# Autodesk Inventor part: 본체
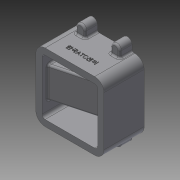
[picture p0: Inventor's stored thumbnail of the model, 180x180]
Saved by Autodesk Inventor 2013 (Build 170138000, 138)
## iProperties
Created: 2018-01
Part Number: 본체
Material: 일반
Document SubType Name: Modeling
Designer: Administrator
Density: 1 g/cm^3
Author: Administrator
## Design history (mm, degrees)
sketch "스케치1"
  geometry: L1 (55, 55)-(-55, 55); L2 (-55, 55)-(-55, -55); L3 (-55, -55)-(55, -55); L4 (55, -55)-(55, 55); L5 (55, 55)-(-55, -55); L6 (-55, 55)-(55, -55); 1 further point
  constraints: 12 end point, 2 midpoint, 2 parallel, 1 horizontal, 1 perpendicular
  dimensions: "d0" = 110 distance of L3.end L2.end; "d1" = 110 distance of L2.end L1.end
extrude "돌출1" new body sketch "스케치1" distance "d2" = 65; taper "d3" = 0 deg
sketch "스케치2"
  geometry: L1 (-55, -55)-(55, -55) reference; L2 (55, -55)-(55, 55) reference; L3 (55, 55)-(-55, 55) reference; L4 (-55, 55)-(-55, -55) reference; L5 (-45, 45)-(45, 45); L6 (45, 45)-(45, -45); L7 (45, -45)-(-45, -45); L8 (-45, -45)-(-45, 45); 1 further point
  constraints: 8 end point, 3 other
  dimensions: "d4" = 10 distance between parallel lines of L2 L6
extrude "돌출2" cut sketch "스케치2" distance "d5" = 65; taper "d6" = 0 deg
sketch "스케치3"
  geometry: L1 (55, 55)-(-55, 55) reference; L2 (-55, -55)-(55, -55) reference; L3 (-35.5, 55)-(-35.5, 65); L4 (-20.5, 65)-(-20.5, 55); L5 (-55, 55)-(-55, -55) reference; L6 (55, -55)-(55, 55) reference; L7 (-55, 0)-(55, 0); L8 (0, 55)-(0, -55); L9 (35.5, 55)-(35.5, 65); L10 (20.5, 65)-(20.5, 55); L11 (20.5, -65)-(20.5, -55); L12 (35.5, -55)-(35.5, -65); L13 (-35.5, -55)-(-35.5, -65); L14 (-20.5, -65)-(-20.5, -55); L15 (-35.5, 55)-(-20.5, 55); L16 (20.5, 55)-(35.5, 55); L17 (-35.5, -55)-(-20.5, -55); L18 (20.5, -55)-(35.5, -55); A1 r 7.5 centre (-28, 65) between (-20.5, 65) and (-35.5, 65); A2 r 7.5 centre (28, 65) between (35.5, 65) and (20.5, 65); A3 r 7.5 centre (28, -65) between (20.5, -65) and (35.5, -65); A4 r 7.5 centre (-28, -65) between (-35.5, -65) and (-20.5, -65); 1 further point
  constraints: 28 end point, 15 symmetric about line, 8 point on circle, 4 centre point, 4 collinear, 4 midpoint, 2 perpendicular, 2 point on line, 2 tangent, 3 other
  dimensions: "d7" = 7.5 radius of A1; "d9" = 10 distance of L3.start L3.end; "d10" = 27 horizontal distance of L1.end A1.centre
extrude "돌출3" join sketch "스케치3" distance "d11" = 20; taper "d12" = 0 deg
sketch "스케치4"
  geometry: L1 (-45, 0)-(-45, -65) reference; L2 (-45, 0)-(45, 0) reference; L3 (-45, -56.436)-(35, -35); L4 (35, -35)-(35, 0); L5 (55, 0)-(55, -65) reference; 1 further point
  constraints: 4 end point, 2 point on line, 1 perpendicular
  dimensions: "d13" = 20 distance between parallel lines of L5 L4; "d14" = 30 vertical distance of L5.end L3.end; "d15" = 105 deg angle of L1 L3
extrude "돌출4" join sketch "스케치4" stored distance "d16" = 50; taper "d17" = 0 deg
sketch "스케치5"
  geometry: L1 (-55, 55)-(-55, -55) reference; L2 (-55, 7.5)-(-36, 7.5); L3 (-36, 7.5)-(-36, 16); L4 (-36, 16)-(-22, 16); L5 (-22, 16)-(-22, 20); L6 (-22, 20)-(25, 20); L7 (25, 20)-(25, 15); L8 (25, 15)-(30, 15); L9 (30, 15)-(30, 0); L10 (30, 0)-(-55, 0); L11 (-55, 0)-(-55, 7.5); 2 further points
  constraints: 20 end point, 6 parallel, 2 midpoint, 2 perpendicular, 1 collinear, 1 horizontal alignment, 1 point on line
  dimensions: "d18" = 30 diameter of L8 L10; "d20" = 40 diameter of L6 L10; "d21" = 32 diameter of L4 L10; "d22" = 15 diameter of L2 L10; "d23" = 19 distance of L2.start L2.end; "d24" = 14 distance of L3.end L4.end; "d25" = 47 distance of L5.end L6.end; "d26" = 5 distance of L7.end L8.end
revolve "회전1" sketch "스케치5" stored, may be unused: angle "d27" = 90 deg
sketch "스케치6"
  geometry: L1 (35, -35)-(-45, -56.436) reference; L2 (20, -33.843)-(-55, -53.939); L3 (-55, -35.939)-(-17, -25.757); L4 (-17, -25.757)-(-17, -10); L5 (20, -10)-(20, -33.843); L6 (25, -20)-(-22, -20) reference; L7 (-55, 0)-(-55, -65) reference; L8 (-17, -10)-(20, -10); L9 (-55, -53.939)-(-55, -35.939); 1 further point
  constraints: 12 end point, 3 parallel, 2 point on line, 1 collinear, 1 vertical
  dimensions: "d28" = 5 distance between parallel lines of L1 L2; "d29" = 5 distance from line of L4 L6.end; "d30" = 5 distance from line of L6.start L5; "d31" = 18 distance of L2.end L3.start; "d32" = 10 distance between parallel lines of L6 L8
extrude "돌출5" cut sketch "스케치6" stored distance "d33" = 30; taper "d34" = 0 deg
fillet "모깎기1" dims "d35" = 15, "d36" = 5, "d37" = 3, "d38" = 1
fillet "모깎기2" dims "d39" = 3
sketch "스케치7"
  geometry: L1 (-40, -45)-(40, -45) reference; L2 (45, -40)-(45, 40) reference; L3 (40, 45)-(-40, 45) reference; L4 (-45, 40)-(-45, 28) reference; L5 (-42, 25)-(32, 25) reference; L6 (35, 22)-(35, -22) reference; L7 (32, -25)-(-42, -25) reference; L8 (-45, -28)-(-45, -40) reference; L9 (35.5, 65)-(35.5, 58) reference; L10 (38.5, 55)-(40, 55) reference; L11 (55, 40)-(55, -40) reference; L12 (40, -55)-(38.5, -55) reference; L13 (35.5, -58)-(35.5, -65) reference; L14 (20.5, -65)-(20.5, -58) reference; L15 (17.5, -55)-(-17.5, -55) reference; L16 (-20.5, -58)-(-20.5, -65) reference; L17 (-35.5, -65)-(-35.5, -58) reference; L18 (-38.5, -55)-(-40, -55) reference; L19 (-55, -40)-(-55, -7.5) reference; L20 (-55, -7.5)-(-36, -7.5) reference; L21 (-36, -7.5)-(-36, -15) reference; L22 (-35, -16)-(-22, -16) reference; L23 (-22, -16)-(-22, -19) reference; L24 (-21, -20)-(24, -20) reference; L25 (25, -19)-(25, -15) reference; L26 (25, -15)-(29, -15) reference; L27 (30, -14)-(30, 14) reference; L28 (29, 15)-(25, 15) reference; L29 (25, 15)-(25, 19) reference; L30 (24, 20)-(-21, 20) reference; L31 (-22, 19)-(-22, 16) reference; L32 (-22, 16)-(-35, 16) reference; L33 (-36, 15)-(-36, 7.5) reference; L34 (-36, 7.5)-(-55, 7.5) reference; L35 (-55, 7.5)-(-55, 40) reference; L36 (-40, 55)-(-38.5, 55) reference; L37 (-35.5, 58)-(-35.5, 65) reference; L38 (-20.5, 65)-(-20.5, 58) reference; L39 (-17.5, 55)-(17.5, 55) reference; L40 (20.5, 58)-(20.5, 65) reference; A1 r 5 centre (-40, -40) between (-45, -40) and (-40, -45) reference; A2 r 5 centre (40, -40) between (40, -45) and (45, -40) reference; A3 r 5 centre (40, 40) between (45, 40) and (40, 45) reference; A4 r 5 centre (-40, 40) between (-40, 45) and (-45, 40) reference; A5 r 3 centre (-42, 28) between (-45, 28) and (-42, 25) reference; A6 r 3 centre (32, 22) between (35, 22) and (32, 25) reference; A7 r 3 centre (32, -22) between (32, -25) and (35, -22) reference; A8 r 3 centre (-42, -28) between (-42, -25) and (-45, -28) reference; A9 r 7.5 centre (28, 65) between (35.5, 65) and (20.5, 65) reference; A10 r 3 centre (38.5, 58) between (35.5, 58) and (38.5, 55) reference; A11 r 15 centre (40, 40) between (55, 40) and (40, 55) reference; A12 r 15 centre (40, -40) between (40, -55) and (55, -40) reference; A13 r 3 centre (38.5, -58) between (38.5, -55) and (35.5, -58) reference; A14 r 7.5 centre (28, -65) between (20.5, -65) and (35.5, -65) reference; A15 r 3 centre (17.5, -58) between (20.5, -58) and (17.5, -55) reference; A16 r 3 centre (-17.5, -58) between (-17.5, -55) and (-20.5, -58) reference; A17 r 7.5 centre (-28, -65) between (-35.5, -65) and (-20.5, -65) reference; A18 r 3 centre (-38.5, -58) between (-35.5, -58) and (-38.5, -55) reference; A19 r 15 centre (-40, -40) between (-55, -40) and (-40, -55) reference; A20 r 1 centre (-35, -15) between (-36, -15) and (-35, -16) reference; A21 r 1 centre (-21, -19) between (-22, -19) and (-21, -20) reference; A22 r 1 centre (24, -19) between (24, -20) and (25, -19) reference; A23 r 1 centre (29, -14) between (29, -15) and (30, -14) reference; A24 r 1 centre (29, 14) between (30, 14) and (29, 15) reference; A25 r 1 centre (24, 19) between (25, 19) and (24, 20) reference; A26 r 1 centre (-21, 19) between (-21, 20) and (-22, 19) reference; A27 r 1 centre (-35, 15) between (-35, 16) and (-36, 15) reference; A28 r 15 centre (-40, 40) between (-40, 55) and (-55, 40) reference; A29 r 3 centre (-38.5, 58) between (-38.5, 55) and (-35.5, 58) reference; A30 r 7.5 centre (-28, 65) between (-20.5, 65) and (-35.5, 65) reference; A31 r 3 centre (-17.5, 58) between (-20.5, 58) and (-17.5, 55) reference; A32 r 3 centre (17.5, 58) between (17.5, 55) and (20.5, 58) reference; 5 further points
  constraints: 4 coincident
hole "구멍1" sketch "스케치7" at (-28, 65), (28, 65), (-28, -65), (28, -65) diameter "d40" = 3.242; stored, may be unused: countersink angle "d44" = 90 deg, drill point angle "d46" = 118 deg; dims "d41" = 9, "d42" = 4, "d43" = 2, "d45" = 11
chamfer "모따기1" distance "d47" = 1; stored, may be unused: second distance "d48" = 2, angle "d49" = 45 deg
sketch "스케치8" dims "d0" = 110, "d1" = 110
  geometry: L1 (-7.387, -41.398)-(42.387, -41.398); L2 (42.387, -41.398)-(42.387, -48.602); L3 (42.387, -48.602)-(-7.387, -48.602); L4 (-7.387, -48.602)-(-7.387, -41.398); L5 (-37.5, 0)-(-37.5, -65) reference; L6 (57.5, -65)-(-22.5, -65) reference; 6 further points
  constraints: 4 midpoint, 2 horizontal alignment, 2 vertical alignment, 2 other
  dimensions: "d50" = 49.77477 distance of L1.start L1.end; "d52" = 7.20489 distance of L1.end L2.end; "d53" = 55 distance from line of L5 point (17.5, -45); "d54" = 20 distance from line of L6 point (17.5, -45)
feature "엠보싱1" sketch "스케치8" dims "d0" = 110, "d1" = 110, "d55" = 0.5, "d56" = 0
node "솔리드1"
node "투영된 루프1"
node "절단 모서리 투영1"
